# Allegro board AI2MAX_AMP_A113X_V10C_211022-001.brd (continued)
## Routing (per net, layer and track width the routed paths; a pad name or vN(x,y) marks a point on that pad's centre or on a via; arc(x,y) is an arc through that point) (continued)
VCC5V: length 170.9
  TOP w0.2: R6.2 34.96,6.79 R18.1
  TOP w0.25: R6.2 34.71,7.64 34.5,7.85 v1(34.5,8.65) ; v1(21,16.5) 21,18.1 20.25,18.85 R10.2 C10.2
  TOP w0.3: v1(73.7,38.3) 73.6,38.4 73.6,40.25 72.85,41 UNK5R5.1 ; v1(89.25,19.1) 89.25,19.25 88.85,19.65 87.75,19.65 86.95,18.85 82.1,18.85 81.85,19.1 81.6,19.1 81,19.7 78.6,19.7 v1(77.03,21.27)
  TOP w0.4: v1(55.65,9.95) v1(56.25,9.35) ; v1(45.55,9.95) v1(46.15,9.35)
  TOP w0.5: v1(44.95,9.95) 44.53,10.37 44.17,10.37 ; v1(44.95,9.95) 44.05,9.95 43.9,10.1 ; v1(44.95,9.95) v1(44.95,9.35) ; v1(44.95,9.95) 44.95,10.45 C57.1 ; v1(44.95,9.95) v1(45.55,9.95) ; 45.55,9.65 44.17,9.65 R52.2 ; 45.55,9.65 v1(45.55,9.35) ; 45.55,9.65 v1(45.55,9.95) ; v1(46.15,9.95) 45.3,10.8 44.7,10.8 ; v1(46.15,9.95) v1(46.15,9.35) v1(45.55,9.35) ; v1(46.15,9.95) v1(45.55,9.95) ; 43.9,10.1 44.17,10.37 ; 43.9,10.1 R52.2 ; 43.9,10.1 43.9,10.75 43.85,10.8 ; 43.9,10.1 43.2,10.8 ; C68.1 55.4,10.8 v1(56.25,9.95) ; C68.1 55.65,10.45 v1(55.65,9.95) ; C68.1 54.8,10.8 ; U3.5 C14.2 ; 43.2,10.8 43.85,10.8 ; 43.2,10.8 C58.2 U52.5 ; 43.85,10.8 C57.1 ; v1(55.65,9.95) v1(55.65,9.35) v1(56.25,9.35) v1(56.25,9.95) ; v1(55.65,9.95) v1(56.25,9.95) ; v1(55.65,9.95) 54.8,10.8 ; v1(45.55,9.95) 44.7,10.8 ; 44.7,10.8 C57.1 ; 44.17,10.37 C57.1 ; R52.2 43.93,9.35 v1(44.95,9.35) ; v1(78.1,26.35) v1(78.1,32.3) v1(78.1,39.1) ; v1(45.55,9.35) v1(44.95,9.35) ; 54.8,10.8 C69.2 U53.5
  MID2(L3) w0.5: 57.55,9.95 62.25,9.95 72.83,20.52 76.28,20.52 v1(77.03,21.27) 77.45,21.7 77.45,23.6 78.1,24.25 v1(78.1,26.35) ; 57.55,9.95 57.2,9.95 ; 57.55,9.95 56.35,8.75 ; v1(73.7,38.3) 74.5,39.1 v1(78.1,39.1) ; v1(56.25,9.35) 56.6,9.35 57.2,9.95 ; v1(56.25,9.35) 56.85,9.95 ; v1(56.25,9.35) v1(55.65,9.35) ; 57.2,9.95 56.85,9.95 ; 56.85,9.95 v1(56.25,9.95)
  BOTTOM w0.1: R330.1 77.85,31.35 R329.1 77.9,32.1 v1(78.1,32.3)
  BOTTOM w0.2: v1(46.15,9.35) R337.2
  BOTTOM w0.25: R17.1 v1(40,8.65)
  BOTTOM w0.4: v1(89.25,19.1) 89.25,11.95 91.1,10.1 93.7,10.1 96.25,7.55 UNK5C13.2 J814.1
  BOTTOM w0.5: 23.3,5.65 23.3,9.7 21,12 v1(21,16.5) ; 23.3,5.65 v1(23.9,5.05) ; 23.3,5.65 v1(23.3,5.05) ; v1(23.9,5.05) v1(23.3,5.05) ; v1(23.9,5.05) v1(24.5,4.45) ; v1(23.9,5.05) v1(24.5,5.05) v1(24.5,4.45) ; v1(23.3,5.05) v1(23.3,4.45) ; v1(23.3,5.05) v1(23.9,4.45) v1(24.5,3.85) ; v1(23.9,3.85) v1(23.3,3.85) v1(23.3,4.45) ; v1(23.9,3.85) v1(23.3,4.45) ; v1(23.9,3.85) v1(24.5,3.85) ; v1(34.5,8.65) v1(35.1,9.25) ; v1(34.5,8.65) v1(35.1,8.65) v1(35.1,9.25) ; v1(34.5,8.65) v1(33.9,8.65) ; v1(35.1,9.25) v1(34.5,9.25) ; U51.5 C52.2 C51.1 46.15,10.45 v1(46.15,9.95) ; v1(56.25,9.35) v1(56.25,9.95) v1(55.65,9.95) ; v1(56.25,9.35) v1(55.65,9.35) v1(55.65,9.95) ; v1(56.25,9.35) v1(55.65,9.95) ; v1(24.5,4.45) v1(24.5,3.85) ; v1(33.9,8.65) v1(33.9,9.25) v1(34.5,9.25) ; v1(33.9,8.65) v1(34.5,9.25) ; v1(78.1,39.1) 79.1,38.1 R334.1
VCC_3.3V: length 71.6
  TOP w0.25: UNK4C4.2 49.64,29.71 UNK4U5.24 ; v1(43.58,52.33) 43.64,52.27 UNK4U5.37 ; UNK4U5.12 43.64,30.43 v1(43.55,30.34) ; UNK4U5.1 38.14,29.31 UNK4C5.1
  TOP w0.254: v2(60.45,51.23) 60.39,51.17 U1.A5 ; U1.K15 66.89,44.92 v2(67.18,45.21)
  TOP w0.3: v1(49.65,28.8) UNK4C4.2 ; UNK4U9.M6 43.01,42.11 v1(43,42.1) UNK4U9.N5 ; UNK4U9.U9 44.51,40.59 v1(44.5,40.6) UNK4U9.T10
  TOP w0.406: v2(59.64,56.26) 59.64,53.6 60.45,52.78 v2(60.45,51.23)
  TOP w0.5: UNK4C4.2 50.85,29.7 51.15,30 v1(51.15,33) ; 38.15,29.05 v1(38.75,28.45) v1(38.15,28.45) 38.15,29.05 ; 38.15,29.05 UNK4C5.1 ; v1(39,62.35) v1(39,59.1) ; v1(78.7,51.7) v1(78.7,54.15)
  MID2(L3) w0.5: v1(78.7,51.7) 78.25,51.7 75.3,48.75 74.25,48.75 71.75,46.25 68.22,46.25 v2(67.18,45.21)
  BOTTOM w0.2: UNK2R19.1 v1(48.2,55.5) ; UNK2R18.1 v1(48.2,58.8)
  BOTTOM w0.3: v1(43.58,52.33) 43.56,52.3 UNK4C8.2
  BOTTOM w0.381: UNK2C22.2 60.35,51.13 v2(60.45,51.23) ; UNK5C10.2 67.42,44.98 v2(67.18,45.21)
  BOTTOM w0.4: UNK4C18.2 44.75,40.35 v1(44.5,40.6) ; UNK4C17.2 v1(43,42.1)
  BOTTOM w0.5: 38.45,28.45 v1(38.15,28.45) 38.15,29.55 ; 38.45,28.45 v1(38.75,28.45) 38.75,28.95 38.45,29.25 ; 38.45,28.45 38.45,29.25 ; 38.15,29.55 C22.1 Q1.3 ; 38.15,29.55 38.45,29.25 ; v1(49.65,28.8) 43.85,28.8 43.55,29.1 UNK4C49.2 v1(43.55,30.34) ; U55.3 51.1,32.95 v1(51.15,33) 51.5,33.35 51.5,34.5 C79.1 U55.1 49.75,34.85 48.55,36.05 v1(47.75,36.05) UNK4R6.2 ; UNK2T15.1 38,63.35 v1(39,62.35)
VDD_EE: length 100.4
  TOP w0.2: v1(38.7,5.05) 38.9,5.05 UNK1R2.2 C64.2 R53.2
  TOP w0.254: 61.02,45.55 60.77,45.3 60.73,45.3 v2(60.72,45.29) 60.7,45.26 U1.J5 ; 61.02,45.55 60.78,45.8 60.62,45.8 U1.J5 ; 61.02,45.55 U1.J6 ; U1.J5 v2(60.06,45.86) U1.J4 v2(59.41,45.85) U1.J3
  TOP w0.3: U1.F12 v2(64.62,47.2) ; U1.K11 v2(63.97,45.24)
  TOP w0.5: v1(51.15,45.75) v1(51.15,45.15)
  MID2(L3) w0.2: 45.15,15.5 44.85,15.2 ; 45.15,15.5 44.85,15.8 ; 45.15,15.5 45.15,15.2 ; 44.85,15.2 44.85,15.8 ; 44.85,15.2 45.15,15.2 ; 44.85,15.2 v1(44.4,15.65) ; 44.85,15.2 45.15,14.9 ; 45.15,14.9 47.85,12.2 61.7,12.2 75.85,26.35 v1(76.6,26.35) ; 45.15,14.9 45.15,15.2 ; 44.85,15.8 v1(44.4,16.25)
  MID2(L3) w0.3: v2(63.97,45.24) 63.35,45.86 v2(60.06,45.86)
  BOTTOM w0.1: UNK2C11.2 56.4,45.85 56.4,45.85 ; 54.94,45.65 55.08,45.51 UNK2C13.1
  BOTTOM w0.2: 44.4,15.5 v1(44.4,15.65) ; 44.4,15.5 44.4,15.05 ; 44.4,15.5 44.17,15.28 ; 44.4,15.05 44.4,12.15 43.6,11.35 43.6,5.95 42.7,5.05 v1(38.7,5.05) ; 44.4,15.05 44.17,15.28 ; R333.2 79.9,26.9 77.15,26.9 v1(76.6,26.35) ; UNK2R27.2 64.85,46.96 v2(64.62,47.2) ; 44.17,15.28 v1(43.8,15.65)
  BOTTOM w0.25: R15.2 42.8,17.25 v1(43.8,16.25)
  BOTTOM w0.3: UNK2C16.2 64.16,46.74 v2(64.62,47.2) 64.87,47.45 UNK2C1.2
  BOTTOM w0.381: UNK2C20.2 60.59,45.85 60.72,45.72 v2(60.72,45.29)
  BOTTOM w0.4: v2(63.97,45.24) 63.97,45.63 UNK2C16.2
  BOTTOM w0.5: v1(43.8,16.25) v1(43.8,15.65) v1(44.4,15.65) ; v1(43.8,16.25) v1(44.4,15.65) ; v1(43.8,16.25) v1(44.4,16.25) v1(44.4,15.65) ; 52.65,45.65 52.65,45.9 51.3,45.9 v1(51.15,45.75) v1(51.15,45.15) 51.65,45.65
  BOTTOM w0.508: UNK2C20.2 v2(59.41,45.85) 55.08,45.85 55.08,45.52
  BOTTOM w1.016: 51.65,45.65 54.94,45.65
VDDAO_3.3V: length 203.8
  TOP w0.1: v1(32,22.95) 32,23.65 32.4,24.05 R350.1 R351.1 ; v1(73.45,59.8) UNK2R24.1 UNK2R28.1
  TOP w0.2: R62.1 56.8,8.4 57.25,8.85 v1(57.25,11.2)
  TOP w0.25: v1(31.1,5.95) 30.46,6.59 C19.2 R8.2 ; v1(86.2,58.25) 87.05,59.1 R349.1 R348.1
  TOP w0.254: v2(66.57,44.59) U1.K14 ; U1.D13 65.59,48.82 v2(65.27,49.15)
  TOP w0.3: v1(86.2,58.25) 86.35,58.1 86.35,49.8 v1(86.45,49.7) ; v1(55.1,61.45) UNK2D7.1
  TOP w0.4: v1(54.75,52.25) 54.05,52.95 54.05,56.8 53.65,57.2 v1(53.65,58)
  TOP w0.5: v1(77.45,27.35) v1(77.45,32.3) v1(77.45,37.9) ; v3(67.55,56.05) 67.55,57.2 UNK2U2.3 68.23,59.37 v1(68.05,59.55) UNK2C15.2 ; v1(44.7,71.4) v1(44.1,71.4) ; v1(36.85,34.55) v1(36.85,35.15)
  MID2(L3) w0.2: 37.2,14.9 36.9,15.2 ; 37.2,14.9 37.2,15.2 ; 37.2,14.9 37.2,12.55 38.55,11.2 v1(57.25,11.2) ; 36.9,15.2 36.45,15.65 ; 36.9,15.2 37.2,15.2 ; v1(86.45,49.7) 86.05,49.3 86.05,42.8 81.15,37.9 v1(77.45,37.9) ; 37.2,15.2 37.2,15.5 37.05,15.65 36.9,15.5
  MID2(L3) w0.5: 44.7,70.8 v1(44.7,71.4) v1(44.1,71.4) 44.7,70.8 ; 44.7,70.8 45.7,69.8 45.7,61 ; v1(89.6,26.12) 88.02,27.7 v1(86.85,27.7) 77.8,27.7 v1(77.45,27.35) ; 59.85,61.7 59.85,71.42 UNK2CON1.3
  BOTTOM w0.1: v1(77.45,32.3) 75,32.3 R336.1
  BOTTOM w0.2: R314.2 27.43,59.01 v1(27.45,59.03) ; v1(89.6,26.12) 89.62,26.14 R214.2 ; R307.1 27.43,25.12 v1(27.45,25.1) ; R323.1 27.43,47.07 v1(27.45,47.05)
  BOTTOM w0.25: v1(33.26,14.89) 33.26,10.06 31.1,7.9 v1(31.1,5.95)
  BOTTOM w0.254: v2(65.27,49.15) 65.36,49.18 66.01,49.84 UNK2C5.2
  BOTTOM w0.3: U302.40 28.87,57.01 C330.1 v1(30.3,57.4) ; 66.98,51.28 66.98,51.28 UNK2C5.2 ; U201.40 88.18,50.08 C201.1 86.46,49.69 v1(86.45,49.7) ; U202.40 88.18,28.13 C230.1 86.89,27.74 v1(86.85,27.7) ; v1(30.05,35.45) C301.1 28.87,35.06 U301.40
  BOTTOM w0.305: v2(66.57,44.59) 66.71,44.45 69.09,44.45 C101.2
  BOTTOM w0.4: v1(54.75,52.25) 56.61,50.39 UNK2R2.1 ; T319.1 T129.1 71.16,61 v1(72.05,61)
  BOTTOM w0.5: v1(77.45,37.9) 77.45,37.3 R335.1 77.15,37.15 76.2,36.2 73.3,36.2 72.8,36.7 72.8,39.4 70.77,41.43 70.77,42.77 C101.2 ; 35.3,34.5 35.3,33.85 ; 35.3,34.5 C21.1 ; 35.3,34.5 R12.2 36.6,34.9 ; 35.3,34.5 36.2,34.5 ; 35.3,33.85 C23.2 C21.1 ; 35.3,33.85 35.55,33.85 36.2,34.5 ; 36.6,34.9 36.2,34.5 ; 36.6,34.9 v1(36.85,35.15) v1(36.85,34.55) 36.15,33.85 C21.1 ; v1(33.26,14.89) v1(33.26,15.49) v1(33.86,15.49) ; v1(33.26,14.89) v1(33.86,15.49) ; v1(33.26,14.89) v1(33.86,14.89) v1(33.86,15.49) ; C21.1 36.15,32.3 Q1.2 ; T316.1 45.35,67.9 C250.2 45.35,71.35 C249.1 v1(44.7,71.4) v1(44.1,71.4) ; v1(56.2,57.85) 56.2,56.86 R105.1
  BOTTOM w0.508: 66.98,51.28 67.82,52.12 67.82,55.78 v3(67.55,56.05)
VDDCPU: length 53.9
  TOP w0.2: U1.G6 61.36,47.19 61.36,47.2 61.04,47.52 U1.F6 60.71,47.2 ; U1.G6 U1.H5 60.06,46.55 ; U1.G6 61.36,46.55 61.37,46.55 v2(61.33,46.59) ; U1.G6 60.71,47.2 ; 60.71,47.2 U1.F5 60.06,47.2 ; 60.71,47.2 v2(60.68,47.2) ; 60.71,47.2 U1.G5 ; 60.06,47.2 U1.G5 ; 60.06,47.2 U1.G4 ; 60.06,46.55 59.9,46.71 ; 60.06,46.55 U1.H4 v2(59.42,46.6) ; 60.06,46.55 v2(60.08,46.59) ; 60.06,46.55 U1.G5 ; 59.9,46.71 U1.G4 ; 59.9,46.71 U1.G4 ; U1.G5 60.71,46.59 v2(60.69,46.59) ; v2(59.42,46.6) U1.H3 ; v2(59.42,46.6) U1.G3 59.09,46.87 v2(59.41,47.2) U1.G4 ; v2(59.42,46.6) U1.G4 ; v1(47.3,15.05) 47.3,14.55 47.9,13.95 47.9,6.65 48.25,6.3 v1(52.45,6.3)
  TOP w0.5: v1(46.7,16.25) v1(47.3,15.65) ; v1(46.7,16.25) v1(47.3,16.25) v1(47.3,15.65) ; v1(46.7,16.25) v1(46.7,15.65) ; v1(47.3,15.65) v1(46.7,15.65) ; v1(47.3,15.65) v1(47.3,15.05) ; v1(46.7,15.65) v1(47.3,15.05) ; v1(46.7,15.65) v1(46.7,15.05) v1(47.3,15.05) ; v1(51.55,50.1) v1(51.55,50.7) ; v1(51.55,50.1) v1(52.15,50.1) ; v1(51.55,50.1) v1(50.95,50.7) ; v1(51.55,50.1) v1(50.95,50.1) v1(50.95,50.7) ; v1(51.55,50.7) v1(52.15,50.7) v1(52.15,50.1) ; v1(51.55,50.7) v1(50.95,50.7) ; v1(51.55,50.7) v1(52.15,50.1)
  BOTTOM w0.1: v2(59.42,46.6) 59.41,46.61 v2(59.41,47.2) ; UNK2C8.2 57.81,46.9 57.8,46.89 ; 58.9,46.89 58.88,46.91 UNK2C14.2 ; UNK2C7.2 56.72,46.91 56.7,46.89 ; v2(60.68,47.2) UNK2C19.2 ; UNK2C6.1 UNK2C4.1 ; 60.2,46.54 60.15,46.59 v2(60.08,46.59)
  BOTTOM w0.102: 61.33,46.57 61.01,46.89 ; 61.33,46.57 61.34,46.56 ; 61.33,46.57 v2(61.33,46.59) ; 61.34,46.56 v2(61.33,46.59) ; 61.34,46.56 61.34,46.56 ; 61.34,46.56 61.35,46.55 61.34,46.56 ; 61.34,46.56 61.44,46.66 v2(61.33,46.59) ; v2(61.33,46.59) 61.34,46.56 ; v2(61.33,46.59) 61.32,46.55 ; 61.34,46.56 61.32,46.55 ; 61.29,46.51 61.32,46.55
  BOTTOM w0.2: v1(52.45,6.3) 51.55,6.3 UNK1R1.2 R51.2 C63.2 ; UNK2C2.2 60.07,47.01 60.2,46.89 ; UNK2C19.2 61.21,46.7 v2(61.33,46.59)
  BOTTOM w0.254: 59.43,46.54 59.43,46.65 v2(59.42,46.6) 59.43,46.54 ; 59.43,46.54 59.84,46.54 60.2,46.89
  BOTTOM w0.406: 61.34,46.57 v2(61.33,46.59) 61.36,46.59 61.36,46.61
  BOTTOM w0.508: 59.84,46.54 61.26,46.54 61.29,46.51 v2(61.33,46.59) ; v2(61.33,46.59) v2(60.69,46.59) ; v2(61.33,46.59) 61.32,46.58
  BOTTOM w1.27: UNK2C4.1 55.63,46.89 61.01,46.89
VDDCPU_EN: length 97.4
  TOP w0.1: v1(47.05,59) 47.7,58.35 48.8,58.35 49.65,57.5 49.65,56.35 50.35,55.65 50.35,52.95 51.25,52.05 53.55,52.05 v1(53.75,51.85) ; v1(45.5,7.45) 46.55,7.45 47.1,8 47.1,13.2 45.8,14.5 45.8,16.8 47.45,18.45 v1(47.45,23.9) ; v1(36.5,23.7) 36.5,26.4 35.65,27.25 35.65,55.6 v1(35,56.25)
  TOP w0.102: U1.C4 v2(59.41,49.8)
  BOTTOM w0.1: v1(53.75,51.85) 54.47,51.85 56.44,49.89 57.26,49.89 UNK2R2.2 57.76,50.4 58.81,50.4 v2(59.41,49.8) ; v1(35,56.25) 35,56.75 35.5,57.25 46.3,57.25 47.05,58 v1(47.05,59) ; v1(47.45,23.9) 42.5,23.9 42,23.4 36.8,23.4 v1(36.5,23.7)
  BOTTOM w0.2: R54.1 v1(45.5,7.45)
VDDCPU_PWM: length 94.2
  TOP w0.1: v1(34.25,53.95) 34.45,53.75 34.45,23.65 36.8,21.3 36.8,4.8 v1(37.05,4.55)
  TOP w0.102: v2(58.76,49.15) U1.D3
  BOTTOM w0.1: v1(34.25,53.95) 35.85,53.95 37.35,55.45 46.3,55.45 47.55,54.2 49.75,54.2 53.8,50.15 55.52,50.15 56.35,49.32 58.59,49.32 v2(58.76,49.15)
  BOTTOM w0.2: v1(37.05,4.55) 37.4,4.2 49.75,4.2 50.4,4.85 R56.2 UNK1R1.1
VDDEE_PWM: length 84
  TOP w0.1: R58.2 UNK1R2.1 39.55,5.05 39.05,4.55 38.1,4.55 37.3,5.35 37.3,21.6 35.25,23.65 35.25,24.05 35.05,24.25 35.05,54.35 34.45,54.95 v1(34.25,54.95)
  TOP w0.102: v2(59.41,49.15) U1.D4
  BOTTOM w0.1: v2(59.41,49.15) 59,49.56 56.45,49.56 55.11,50.9 53.75,50.9 49.95,54.7 47.76,54.7 46.51,55.95 37.05,55.95 36.05,54.95 v1(34.25,54.95)
VDDIO_AO18: length 88.9
  TOP w0.254: U1.H12 v2(65.27,45.9) ; v2(65.27,45.9) U1.J12 ; v2(65.27,45.9) U1.H13 65.83,45.97 v2(65.83,45.9) 65.83,45.81 U1.J13 65.46,45.7 v2(65.27,45.9)
  TOP w0.5: v1(77.45,40.25) 78.05,40.85 78.05,45.9 79.45,47.3 v1(79.45,51.7) v1(79.45,54.1)
  MID2(L3) w0.5: v1(55.07,57.85) 55.82,57.1 62.5,57.1 63.3,57.9 68.08,57.9 v3(68.78,57.2) 69.93,56.05 77.8,56.05 79.45,54.4 v1(79.45,54.1)
  BOTTOM w0.1: v2(65.83,45.9) 65.27,45.9 v2(65.27,45.9) ; 68.1,46.26 UNK3C1.2 ; UNK2C17.1 70.54,46.27 70.55,46.28
  BOTTOM w0.254: 66.37,45.9 66.18,45.7 65.59,45.7 UNK5C9.2
  BOTTOM w0.3: UNK2R29.2 72.95,49.05 75.05,51.15 78.9,51.15 v1(79.45,51.7)
  BOTTOM w0.4: UNK5C9.2 65.27,45.5 v2(65.27,45.9) 66.37,45.9 66.38,45.9
  BOTTOM w0.406: 66.38,45.9 UNK2C10.2
  BOTTOM w0.5: v1(77.45,40.25) UNK5R20.1 ; UNK5R20.1 75.75,41.26 73.1,43.91 73.1,44.91 ; UNK5R20.1 C76.1 U54.5 ; v1(55.07,57.85) R106.1
  BOTTOM w0.508: 70.28,46.16 UNK2C17.1 ; 70.28,46.16 70.18,46.26 68.84,46.26 ; 70.28,46.16 68.74,46.16 ; 68.84,46.26 UNK2C12.2 ; 68.84,46.26 68.1,46.26 67.82,45.98 ; 68.84,46.26 68.74,46.16 ; UNK2C10.2 66.45,45.98 67.82,45.98 ; 67.82,45.98 68.55,45.98 68.74,46.16 ; UNK2R3.2 69.11,53.93 69.11,56.87 v3(68.78,57.2)
  BOTTOM w0.61: 71.83,46.18 71.73,46.28 71.11,46.28 ; 71.83,46.18 73.1,44.91 73.1,45.42 71.95,46.56 UNK2C12.2 ; 71.83,46.18 71.22,46.18 71.11,46.28 ; 70.55,46.28 71.11,46.28
VDDIO_BOOT: length 92.4
  TOP w0.2: UNK4U9.Y4 UNK4U9.W4 ; UNK4U9.Y4 UNK4U9.AA3 v1(41.51,36.95) ; UNK4U9.Y4 UNK4U9.AA5 v1(42.51,36.95) ; v1(45.11,54.36) 44.99,54.48 UNK4R8.1 UNK4R3.1
  TOP w0.25: v1(48.3,53.46) UNK4C11.2 48.14,52.59 UNK4U5.28 ; UNK4U5.45 39.64,51.96 v1(39.15,52.45)
  TOP w0.254: UNK4U5.34 45.14,53.57 UNK4C10.2 45.11,53.64 v1(45.11,54.36)
  TOP w0.3: v2(58.82,44.53) 59.08,44.27 U1.L3 ; v1(43.2,43.1) 43.01,43.29 UNK4U9.K6
  TOP w0.5: v1(51.75,37.45) 51.75,41.15 v1(52.25,41.65) ; v1(37.45,51.3) v1(37.45,44.25) v1(37.45,38.95)
  MID2(L3) w0.5: v1(43.2,43.1) 43.2,43.9 42.85,44.25 37.45,44.25 v1(37.45,44.25) ; 39.51,38.95 v1(37.45,38.95) ; 39.51,38.95 39.7,38.76 ; 39.51,38.95 v1(39.7,38.95) ; v1(44.45,35.2) 44.45,36.15 43.65,36.95 v1(42.51,36.95) 41.7,36.95 ; 41.7,36.95 v1(39.7,38.95) ; 41.7,36.95 v1(41.51,36.95) 39.7,38.76 ; 39.7,38.76 v1(39.7,38.95)
  BOTTOM w0.1: UNK4R12.2 v1(39.7,38.95) ; v1(44.45,35.2) 44.45,31.9 UNK4R4.1 ; UNK4C34.2 43.75,43.6 UNK4R16.1
  BOTTOM w0.2: v1(41.51,36.95) 41.05,36.49 UNK4R14.1 UNK4R1.2 42.15,36.95
  BOTTOM w0.4: v1(43.2,43.1) 43.3,43.2 UNK4C34.2 ; v1(52.25,41.65) 53.85,41.65 54.4,42.2 55.22,42.2 56.53,43.51 56.97,43.51 UNK4C2.2 57.99,44.19 58.33,44.53 v2(58.82,44.53)
  BOTTOM w0.5: v1(37.45,51.3) 37.95,51.8 UNK4C48.2 v1(39.15,52.45) 39.15,52.75 39.98,53.58 42.87,53.58 43.65,54.36 v1(45.11,54.36) 45.64,54.36 46.54,53.46 v1(48.3,53.46) ; v1(41.51,36.95) v1(42.51,36.95) UNK4C35.2 UNK4C47.1 UNK4R5.1 UNK4R6.1 51.25,36.95 v1(51.75,37.45)
VDDIO_X: length 12.4
  TOP w0.254: v2(62.66,49.8) 62.34,49.47 U1.C8
  BOTTOM w0.4: v2(62.66,49.8) 62.66,50.14 62.1,50.7 C102.2 62.1,53.5 61.6,54 60.25,54 58.7,55.55 56.9,55.55 56.51,55.94 R105.2 R106.2
VDDQ1.35V: length 76.3
  TOP w0.2: v2(56.73,31.43) 56.77,31.4 56.78,31.4 57.04,31.13 UNK3U1.F1 ; v2(58.42,34.7) UNK3U1.B2 58.05,34.34 v2(57.65,34.74) 57.26,35.13 UNK3U1.A1 ; v2(64.18,23.94) 64.18,23.94 63.66,23.94 UNK3U1.R9 ; UNK3U1.N9 64.17,25.53 v2(64.17,25.53) ; v2(61.59,30.05) 61.77,30.05 UNK3U1.G7 61.67,30.71 v2(61.62,30.71) ; UNK3U1.C1 56.65,33.53 v2(56.65,33.53) ; 63.68,32.73 UNK3U1.D9 63.65,32.69 v2(63.27,32.31) UNK3U1.E9 63.65,31.94 v2(64.06,32.35) 63.68,32.73 ; 63.68,32.73 63.7,32.73 v2(64.12,33.15) 64.03,33.15 UNK3U1.C9 ; v1(53.5,6.3) 53.5,6.8 52.95,7.35 R61.2 C74.2 ; U1.M10 v2(63.97,43.94) U1.M11 ; v2(56.69,23.83) 56.79,23.93 UNK3U1.R1 ; v2(62.41,35.54) 62.44,35.54 UNK3U1.A8 ; v2(62.44,27.52) UNK3U1.K8 ; UNK3U1.H2 v2(57.69,29.17) ; v2(58.42,28.31) 58.05,27.94 UNK3U1.K2 ; U1.M8 v2(62.01,43.29) 61.69,43.62 U1.M7 v2(61.36,43.29) U1.M6 ; v2(64.12,29.59) 63.71,29.59 63.65,29.54 UNK3U1.H9 ; 60.39,42.97 U1.N5 v2(60.06,42.64) 59.74,42.97 U1.N4 v2(60.06,43.29) 60.39,42.97
  TOP w0.3: UNK3U1.D2 58.44,32.34 v2(58.46,32.34) ; UNK3U1.N1 57.24,25.52 v2(56.68,25.52)
  BOTTOM w0.2: 54.73,13.38 54.5,13.6 ; 54.73,13.38 54.5,13.15 ; 54.73,13.38 v1(55.1,13.75) ; 54.5,13.6 v1(54.5,13.75) ; 54.5,13.6 54.5,13.15 ; 54.5,13.15 54.5,7.3 v1(53.5,6.3)
  BOTTOM w0.3: 64.36,33.39 UNK3C58.2 64.23,33.96 64.1,33.96 ; 64.36,33.39 v2(64.12,33.15) 63.82,32.85 UNK3C38.2 ; 64.36,33.39 64.36,32.65 64.1,32.39 ; 63.6,33.96 UNK3C42.2 63.3,33.95 UNK3C38.2 ; 63.6,33.96 63.8,33.96 ; 63.6,33.96 63.6,32.64 63.31,32.35 ; UNK3C21.2 57,33.18 v2(56.65,33.53) ; 64.1,32.39 v2(64.06,32.35) 63.6,32.35 ; 64.1,32.39 64.1,33.96 ; UNK3C38.2 63.27,32.82 v2(63.27,32.31) 63.31,32.35 ; 63.31,32.35 63.6,32.35 ; UNK3C4.2 64.54,43.37 v2(63.97,43.94) ; 64.1,33.96 63.8,33.96 ; 63.6,32.35 63.8,32.55 63.8,33.96
  BOTTOM w0.381: UNK3C2.2 56.42,31.74 v2(56.73,31.43)
  BOTTOM w0.4: v2(54.34,27.56) 54.87,27.56 UNK3R19.2 54.94,27.49 v2(54.94,26.9) ; 59.55,42.65 59.82,42.65 UNK3C39.2 ; 59.55,42.65 UNK3C62.2 ; 59.55,42.65 60.06,43.16 ; UNK3C62.2 59.16,42.64 v2(60.06,42.64) 60.06,42.71 ; UNK3C62.2 58.35,41.85 UNK3C31.2 56.65,40.28 UNK3C28.1 ; v2(58.42,28.31) 58.42,28.7 UNK3C26.1 ; UNK3C10.2 58.42,35.18 v2(58.42,34.7) ; 60.06,42.71 60.06,43.16 ; 60.06,42.71 60.53,43.18 UNK3C39.2 ; 60.06,43.16 v2(60.06,43.29) 60.13,43.36 UNK3C39.2 ; UNK3C18.2 56.66,25.5 v2(56.68,25.52) 56.8,25.52 UNK3C6.1 ; v2(64.17,25.53) 64.62,25.53 UNK3C30.2 ; UNK3C11.2 58.51,32.28 v2(58.46,32.34) ; v2(61.59,30.05) 61.06,30.05 UNK3C8.1 61.16,30.71 v2(61.62,30.71) ; UNK3C19.2 57.38,29.49 v2(57.69,29.17) ; v2(64.18,23.94) 63.92,24.21 UNK3C12.2 ; v2(57.65,34.74) 57.65,35.12 UNK3C9.2 ; v2(64.12,29.59) 63.62,29.59 UNK3C45.2
  BOTTOM w0.406: v2(62.01,43.29) 61.37,43.29 v2(61.36,43.29)
  BOTTOM w0.5: v2(62.41,35.54) 62.51,35.64 UNK3C20.2 ; UNK3C35.2 56.69,23.42 ; 56.69,23.42 57.17,23.42 UNK3R8.2 ; 56.69,23.42 v2(56.69,23.83) ; v2(56.69,23.83) 57.15,23.37 UNK3R8.2 ; v2(56.69,23.83) 56.81,23.83 57.22,24.24 ; UNK3R8.2 57.22,24.24 ; 57.22,24.24 UNK3C6.1 ; UNK3C19.2 58.2,29.7 58.7,29.2 UNK3C26.1 ; v1(55.1,13.75) v1(54.5,13.75) v1(54.5,14.35) ; v1(55.1,13.75) v1(55.1,14.35) v1(54.5,14.35) ; v1(55.1,13.75) v1(54.5,14.35) ; v2(62.01,43.29) 61.98,43.33 UNK3C5.2
  vias: v4(54.33,38.06) v4(54.35,39.07)
ACTIVE_STBY: length 123.9
  TOP w0.1: v1(60.7,16.5) 60.3,16.9 59.75,16.9 59.5,17.15 59.5,17.6 53.85,23.25 53.85,23.65 53.3,24.2 v1(53,24.2) ; U1.B11 64.62,50.45 64.62,50.93 64.18,51.36 64.18,54.98 64.95,55.75 64.95,58.85 v1(64.75,59.05) ; v1(38.3,25.4) 37.8,25.9 37.3,25.9 35.85,27.35 35.85,56.05 v1(35.65,56.25) ; v1(71.64,15.5) 71.8,15.5 72.6,16.3 79.45,16.3 81,14.75 R219.1
  BOTTOM w0.1: v1(35.65,56.25) 36.25,56.85 46.5,56.85 47.8,58.15 47.8,59.05 48.1,59.35 50.45,59.35 50.75,59.05 v1(64.75,59.05) ; v1(60.7,16.5) 60.9,16.3 70.14,16.3 70.54,15.9 71.24,15.9 v1(71.64,15.5) ; v1(53,24.2) 52.6,24.6 52,24.6 51,25.6 42,25.6 40.7,24.3 38.8,24.3 38.3,24.8 v1(38.3,25.4) 37.75,25.95 R320.1
AMP_RESET: length 105.2
  TOP w0.1: R215.1 v1(82,13.4) 82,14.35 79.65,16.7 72.3,16.7 71.9,16.3 v1(71.64,16.3) ; v1(53,25) 53.1,25 54.25,23.85 54.25,23.42 59.97,17.7 60.3,17.7 v1(60.7,17.3) ; v1(35.85,60.2) 35.7,60.05 35.7,57.45 36.25,56.9 36.25,27.55 37.45,26.35 40.3,26.35 v1(40.65,26)
  BOTTOM w0.1: v1(60.7,17.3) 60.75,17.3 61.35,16.7 71.24,16.7 v1(71.64,16.3) ; UNK5R74.2 v1(82,13.4) ; R315.1 v1(40.65,26) 52,26 v1(53,25) ; v1(35.85,60.2) 35.6,59.95 33.85,59.95 33.55,60.25 33.55,63.9 36.3,66.65 41.6,66.65 42.08,67.12
  BOTTOM w0.3: T317.1 42.08,67.12
AMP_SCL: length 67.4
  TOP w0.1: UNK2R24.2 v1(75,59.05) ; v1(80.75,59) 80.75,57.8 81.3,57.25 81.3,54.25 81.85,53.7 81.85,48.25 82.1,48 82.1,33.55 82.9,32.75 82.9,20.1 v1(83.1,19.9)
  TOP w0.102: v1(75,59.05) 75.4,58.65 75.4,57.8 74.74,57.14 71.86,57.14 69.3,54.57 69.3,53.46 67.54,51.69 U1.A16
  BOTTOM w0.1: v1(83.1,19.9) 82.9,19.7 81.65,19.7 80.2,18.25 80.2,16.3 80.9,15.6 UNK5R66.2 ; v1(80.75,59) 79.75,59 79.15,59.6 76.35,59.6 R209.1 v1(75,59.05)
AMP_SCL_DEV: length 66.1
  TOP w0.1: v1(77.3,61.3) 77.45,61.15 77.45,59.25 v1(77.25,59.05) ; v1(36.15,59.05) 36.55,59.45 36.55,60.65 v1(36.8,60.9) ; R309.1 46.35,57.7 45.8,58.25 v1(45.8,58.45)
  BOTTOM w0.1: v1(36.15,59.05) 36.55,58.65 37,58.65 37.15,58.5 37.7,58.5 38.15,58.05 45.4,58.05 v1(45.8,58.45) ; v1(36.8,60.9) 37.2,61.3 37.2,63.85 37.6,64.25 46.1,64.25 46.65,64.8 61.65,64.8 62.65,65.8 63.2,65.8 64.1,66.7 68.05,66.7 69.2,67.85 69.6,67.85 ; R238.1 v1(77.25,59.05) R209.2 ; 71.2,67.85 71.55,67.85 72.6,66.8 72.6,64.1 75.2,61.5 77.1,61.5 v1(77.3,61.3)
  BOTTOM w0.3: 69.6,67.85 T306.1 71.2,67.85
AMP_SDA: length 69.5
  TOP w0.1: v1(75,57.95) UNK2R28.2 73.75,57.35 71.77,57.35 ; v1(83.75,19.9) 83.1,20.55 83.1,32.87 82.3,33.67 82.3,48.15 82.05,48.4 82.05,53.8 81.51,54.34 81.51,57.74 v1(81.25,58)
  TOP w0.102: U1.B15 66.89,50.27 67.21,50.59 67.21,51.67 69.09,53.55 69.09,54.66 71.77,57.35
  BOTTOM w0.1: v1(83.75,19.9) 83.35,19.5 81.75,19.5 80.4,18.15 80.4,16.4 81.45,15.35 81.45,13.85 80.9,13.3 UNK5R65.2 ; v1(75,57.95) R210.1 76.35,57.4 79.2,57.4 80,58.2 81.05,58.2 v1(81.25,58)
AMP_SDA_DEV: length 69.4
  TOP w0.1: v1(77.95,61.3) 77.65,61 77.65,58.35 v1(77.25,57.95) ; R310.1 46,57.1 46,57.45 45.2,58.25 v1(45.2,58.45) ; v1(36.75,59.05) 36.75,60.25 37.2,60.7 37.2,61.1 v1(36.8,61.5)
  BOTTOM w0.1: R239.1 v1(77.25,57.95) R210.2 ; v1(77.95,61.3) 77.55,61.7 75.3,61.7 72.8,64.2 72.8,67.2 ; 72.22,68.42 72,68.65 69.7,68.65 67.95,66.9 64,66.9 63.1,66 62.55,66 61.55,65 46.55,65 46,64.45 37.45,64.45 37,64 37,61.7 v1(36.8,61.5) ; v1(36.75,59.05) 36.9,59.05 37.25,58.7 37.85,58.7 38.3,58.25 45,58.25 v1(45.2,58.45)
  BOTTOM w0.3: 72.8,67.2 T305.1 72.22,68.42
BCLK: length 5.6
  BOTTOM w0.102: UNK5R68.1 78.5,10.75 79.65,9.6 81.3,9.6 82.18,8.72 J813.11
CPU_RESET: length 126.6
  TOP w0.1: v1(71.65,17.1) 79.85,17.1 81.7,15.25 83.9,15.25 R240.1 ; v1(53,25.7) 54.45,24.25 54.45,23.52 60.07,17.9 60.9,17.9 v1(61.5,17.3) ; v1(37.55,58.05) 37.55,57.65 36.85,56.95 36.85,36.8 37.3,36.35 37.3,34.35 36.65,33.7 36.65,27.6 37.6,26.65 40.25,26.65 v1(40.65,27.05) ; v1(65.55,59.65) 65.55,59.35 65.35,59.15 65.35,57.61 UNK2U2.2 65.74,56.64 UNK2R14.1 65.73,55.47 64.89,54.63 64.89,51.83 64.63,51.56 64.63,51.25 64.94,50.94 U1.A12
  BOTTOM w0.1: v1(53,25.7) 52.5,26.2 41.5,26.2 v1(40.65,27.05) 40.6,27.1 R338.1 ; v1(37.55,58.05) 37.75,57.85 45.95,57.85 46.25,58.15 46.25,59.4 46.7,59.85 47.35,59.85 47.65,60.15 50.9,60.15 51.2,59.85 58.9,59.85 59.3,60.25 60.45,60.25 61.05,59.65 63.6,59.65 64,60.05 65.15,60.05 v1(65.55,59.65) ; v1(61.5,17.3) 61.9,16.9 71.45,16.9 v1(71.65,17.1)
CTRL_A113X: length 2.7
  BOTTOM w0.1: UNK5R75.2 UNK5R77.1 UNK5R76.1
DATA: length 8.2
  BOTTOM w0.102: UNK5R69.1 78,13.65 78,10.65 79.35,9.3 81.1,9.3 81.68,8.72 J813.12
DDR3_A0: length 28.5
  TOP w0.102: v2(64.62,41.34) U1.R12 ; v2(60.55,24.73) 60.08,24.73 59.28,25.53 UNK3U1.N3
  BOTTOM w0.102: v2(64.62,41.34) 64.62,41.21 64.26,40.86 64.26,40.62 64.54,40.34 64.79,40.34 65.91,39.22 66.67,39.22 68.54,37.35 68.54,26.89 66.55,24.89 65.76,24.89 65.53,25.12 63.85,25.12 63.73,25 60.82,25 v2(60.55,24.73)
DDR3_A1: length 24.7
  TOP w0.1: v2(62.44,24.35) 62.06,24.73 UNK3U1.P7
  TOP w0.102: U1.U15 66.95,40.31 66.95,39.68 69.12,37.51 69.12,26.66 66.1,23.64 v2(65.9,23.64)
  BOTTOM w0.102: v2(62.44,24.35) 62.81,23.98 62.81,23.27 63.35,22.74 65.2,22.74 65.9,23.43 v2(65.9,23.64)
DDR3_A2: length 34.8
  TOP w0.102: v2(67.87,41.99) U1.P16 ; v2(59.65,23.76) 59.65,24.3 59.22,24.73 UNK3U1.P3
  BOTTOM w0.102: v2(67.87,41.99) 68.27,41.59 68.27,41.3 68.76,40.82 69.31,40.82 71.3,38.84 71.3,25.76 66.42,20.88 63.09,20.88 60.21,23.76 v2(59.65,23.76)
DDR3_A3: length 35.7
  TOP w0.102: U1.U17 70.43,38.13 70.43,26.11 65.48,21.16 59.41,21.16 58.36,22.21 57.6,22.21 56.34,23.47 56.34,24.98 56.5,25.15 57.39,25.15 57.77,25.53 UNK3U1.N2
DDR3_A4: length 24.6
  TOP w0.102: UNK3U1.P8 63.24,25.12 64.95,25.12 v2(65.35,25.53) ; v2(64.54,41.94) 64.29,41.69 U1.R11
  BOTTOM w0.102: v2(65.35,25.53) 65.54,25.53 65.9,25.17 66.42,25.17 68.25,27 68.25,37.29 66.55,38.98 65.79,38.98 64.65,40.12 64.4,40.12 63.97,40.55 63.97,40.93 64.26,41.23 64.26,41.66 v2(64.54,41.94)
DDR3_A5: length 30.3
  TOP w0.102: UNK3U1.P2 58.22,24.73 58.62,25.14 59.24,25.14 60.03,24.35 60.03,23.56 59.87,23.4 59.87,22.96 60.09,22.74 64.77,22.74 65.15,23.12 65.15,23.9 65.86,24.61 66.27,24.61 68.54,26.89 68.54,37.35 66.44,39.45 66.44,39.91 66.29,40.06 66.11,40.06 65.94,40.23 65.94,40.54 66.17,40.77 66.17,40.94 U1.T14
DDR3_A6: length 24.4
  TOP w0.102: UNK3U1.R8 63.26,24.34 65.05,24.34 v2(65.39,24.68) ; v2(65.27,41.99) U1.P12
  BOTTOM w0.102: v2(65.39,24.68) 65.45,24.61 66.67,24.61 68.83,26.77 68.83,37.42 65.27,40.98 v2(65.27,41.99)
DDR3_A7: length 29.3
  TOP w0.102: UNK3U1.R2 58.44,24.32 59.08,24.32 59.24,24.16 59.24,23.21 59.99,22.46 64.92,22.46 65.45,22.99 65.45,23.8 65.99,24.34 66.39,24.34 68.83,26.77 68.83,37.42 66.7,39.55 66.7,40.06 66.4,40.35 66.24,40.35 U1.U14
DDR3_A8: length 25.1
  TOP w0.102: U1.P13 65.85,42.06 v2(65.85,42.04) ; v2(64.77,23.93) 64.39,23.55 63.27,23.55 UNK3U1.T8
  BOTTOM w0.102: v2(65.85,42.04) 65.56,41.74 65.56,41.07 69.12,37.51 69.12,26.66 66.77,24.31 65.4,24.31 65.02,23.93 v2(64.77,23.93)
DDR3_A9: length 31.6
  TOP w0.102: UNK3U1.R3 58.47,23.55 58.47,22.91 58.62,22.76 58.62,22.35 59.54,21.44 65.38,21.44 70.13,26.19 70.13,38.03 68.15,40.01 68.07,40.01 67.87,40.21 67.87,40.69 U1.T16
DDR3_A10: length 22.8
  TOP w0.102: U1.R10 63.64,41.67 63.89,41.42 v2(63.9,41.42) ; UNK3U1.L7 62.43,26.75 66.72,26.75 v2(67,27.03)
  BOTTOM w0.102: v2(67,27.03) 67.94,27.97 67.94,37.19 66.41,38.72 65.7,38.72 64.56,39.85 64.3,39.85 63.66,40.49 63.66,41.18 v2(63.9,41.42)
DDR3_A11: length 35.3
  TOP w0.102: U1.P17 68.2,42.32 v2(68.53,41.99) ; v2(60.25,23.14) 60.35,23.04 61.42,23.04 62.05,23.67 UNK3U1.R7
  BOTTOM w0.102: v2(60.25,23.14) 60.45,23.14 62.99,20.6 66.55,20.6 71.58,25.63 71.58,38.97 69.44,41.1 68.88,41.1 68.56,41.42 68.56,41.97 68.54,41.99 v2(68.53,41.99)
DDR3_A12: length 30.8
  TOP w0.102: U1.T17 68.19,41.02 68.58,41.02 69.04,40.57 v2(69.04,40.08) ; v2(61.42,23.62) 61.41,23.63 61.67,23.89 61.67,25.15 UNK3U1.N7
  BOTTOM w0.102: v2(61.42,23.62) 61.42,23.34 63.32,21.44 66.17,21.44 70.74,26.01 70.74,38.38 v2(69.04,40.08)
DDR3_A13: length 29
  TOP w0.102: UNK3U1.T3 58.94,23.13 59.89,22.18 65.07,22.18 69.42,26.52 69.42,37.59 67.21,39.8 67.21,41.31 66.87,41.65 U1.R15
DDR3_A14: length 27.6
  TOP w0.1: v2(62.42,23.51) 62.05,23.14 UNK3U1.T7
  TOP w0.102: v2(66.51,41.42) 66.49,41.42 U1.R14
  BOTTOM w0.102: v2(66.51,41.42) 66.74,41.42 70.13,38.03 70.13,26.19 66.39,22.46 63.21,22.46 62.42,23.24 v2(62.42,23.51)
DDR3_A15: length 29.2
  TOP w0.102: UNK3U1.M7 61.29,25.57 v2(61.29,24.54) ; v2(65.92,41.34) 65.59,41.02 U1.T13
  BOTTOM w0.102: v2(61.29,24.54) 61.47,24.72 62.66,24.72 63.14,24.23 63.14,23.88 63.32,23.7 63.9,23.7 64.03,23.57 65.12,23.57 65.58,24.03 66.93,24.03 69.42,26.52 69.42,37.63 67.64,39.41 67.64,40.13 66.72,41.05 66.21,41.05 v2(65.92,41.34)
DDR3_BA0: length 41
  TOP w0.102: UNK3U1.M2 57.66,25.94 56.47,25.94 56.03,25.49 56.03,23.37 57.45,21.95 58.21,21.95 59.28,20.88 65.61,20.88 70.74,26.01 70.74,38.39 69.47,39.66 69.47,41.62 68.31,42.78 67.75,42.78 67.56,42.97 U1.N16
DDR3_BA1: length 20.5
  TOP w0.102: U1.U12 64.94,40.01 65.12,39.83 65.12,39.65 65.78,38.99 66.14,38.99 67.94,37.19 67.94,27.1 66.77,25.94 63.26,25.94 UNK3U1.N8
DDR3_BA2: length 45
  TOP w0.102: UNK3U1.M3 58.44,26.74 56.55,26.74 55.73,25.91 55.73,23.37 58.77,20.32 65.86,20.32 71.3,25.76 71.3,38.84 70,40.13 70,41.76 68.48,43.28 68.01,43.28 67.67,43.62 U1.M16
DDR3_CAS: length 35.4
  TOP w0.102: UNK3U1.K3 59.82,27.93 60.91,26.85 v2(60.91,23.98) ; U1.P15 66.89,42.32 v2(66.57,41.99)
  BOTTOM w0.102: v2(60.91,23.98) 61.56,23.98 61.92,23.62 61.92,23.31 63.06,22.18 66.5,22.18 70.43,26.11 70.43,38.13 v2(66.57,41.99)
DDR3_CKE0: length 19
  TOP w0.102: v2(66.55,28.17) 65.94,28.17 65.7,27.94 63.66,27.94 UNK3U1.K9 ; U1.P10 63.64,42.32 v2(63.32,41.99)
  BOTTOM w0.102: v2(63.32,41.99) 63.3,41.99 62.9,41.59 62.9,39.93 66.5,36.34 66.5,28.22 v2(66.55,28.17)
DDR3_CLKN: length 20.6
  TOP w0.102: v2(65.33,28.58) 66.42,29.67 66.42,36.25 64.57,38.1 UNK3C7.1 64.14,38.43 63.66,38.9 63.66,39.37 63.65,39.39 63.65,39.4 63.32,39.73 63.32,40.6 63.63,40.91 63.63,41.01 U1.T10 ; v2(61.3,28.04) 61.33,28.07 61.45,28.2 61.96,28.2 62.05,28.1 UNK3U1.K7
  BOTTOM w0.102: v2(65.33,28.58) 65.33,28.56 65.19,28.43 61.8,28.43 61.45,28.08 61.42,28.08 v2(61.3,28.04) 61.29,28.05 61.29,28.06 61.15,28.21 60.94,28.21 UNK3R2.2
DDR3_CLKP: length 19.4
  TOP w0.102: U1.U9 63.04,40.32 63.04,39.6 63.38,39.26 63.38,38.79 63.85,38.32 UNK3C7.2 64.56,37.71 66.14,36.13 66.14,29.8 65.62,29.28 65.42,29.28 v2(65.4,29.26) ; v2(61.26,28.68) 61.31,28.64 61.48,28.48 61.97,28.48 62.05,28.55 UNK3U1.J7
  BOTTOM w0.1: UNK3R2.1 61.09,28.68 v2(61.26,28.68)
  BOTTOM w0.102: v2(61.26,28.68) 61.32,28.64 61.38,28.7 64.84,28.7 v2(65.4,29.26)
DDR3_DQ0: length 7.1
  TOP w0.1: 57.12,36.06 57.12,36.06 UNK3U1.A2
  TOP w0.102: U1.T2 58.44,41.02 58.28,41.02 57.95,40.69 57.66,40.69 57.12,40.16 57.12,36.06
DDR3_DQ1: length 9.9
  TOP w0.102: U1.T3 59.08,41.01 59.08,40.87 58.77,40.57 58.77,39.79 58.44,39.46 58.44,36.79 59.51,35.73 59.51,33.66 58.98,33.13 58.67,33.13 58.27,33.53 UNK3U1.C2
DDR3_DQ2: length 8.3
  TOP w0.102: v2(60.71,41.99) U1.P6 ; UNK3U1.A7 61.82,35.36 61.82,35.88 v2(61.92,35.98)
  BOTTOM w0.102: v2(60.71,41.99) 60.71,41.99 61.14,41.57 61.14,41.02 60.81,40.69 60.81,37 61.8,36 61.9,36 v2(61.92,35.98)
DDR3_DQ3: length 10.3
  TOP w0.102: U1.U7 61.85,40.24 61.85,37.09 63.04,35.89 63.69,35.89 64.01,35.58 64.01,34.15 63.79,33.94 63.45,33.94 63.26,33.74 63.26,33.37 63.03,33.14 62.55,33.14 62.14,32.73 UNK3U1.D7
DDR3_DQ4: length 6.1
  TOP w0.102: UNK3U1.A3 58.39,35.59 58.13,35.59 57.43,36.29 57.43,40.01 U1.U1
DDR3_DQ5: length 7.6
  TOP w0.102: UNK3U1.C3 58.86,33.53 59.21,33.88 59.21,35.58 58.14,36.64 58.14,39.59 58.44,39.89 U1.U2
DDR3_DQ6: length 8.5
  TOP w0.102: UNK3U1.B8 v2(62.44,34.74) ; U1.R6 61.04,41.66 v2(60.78,41.4)
  BOTTOM w0.102: v2(60.78,41.4) 60.78,41.05 60.5,40.77 60.5,36.85 62.44,34.9 v2(62.44,34.74)
DDR3_DQ7: length 8.6
  TOP w0.102: UNK3U1.C8 62.85,33.81 63.24,34.21 63.24,35.26 61.54,36.96 61.54,40.05 61.36,40.22 61.36,40.55 61.69,40.87 U1.T7
DDR3_DQ8: length 15.3
  TOP w0.102: UNK3U1.H7 62.29,29.53 62.74,29.97 64.3,29.97 65,30.67 65,35.61 64.01,36.6 63.37,36.6 62.56,37.42 62.56,38.99 62.25,39.3 62.25,40.93 U1.T8
DDR3_DQ9: length 13.7
  TOP w0.102: UNK3U1.F2 57.66,31.52 57.15,31.52 56.84,31.83 56.28,31.83 55.62,32.49 55.62,35.79 56.41,36.58 56.41,40.27 57.48,41.34 57.9,41.34 58.25,41.69 58.43,41.69 U1.R2
DDR3_DQ10: length 16.2
  TOP w0.102: U1.R9 62.66,41.34 62.66,40.86 62.48,40.68 62.48,39.38 62.86,39 62.86,37.56 63.54,36.88 64.18,36.88 65.3,35.77 65.3,30.52 64.49,29.71 64.49,29.46 64.2,29.17 63.21,29.17 UNK3U1.H8
DDR3_DQ11: length 11
  TOP w0.1: v2(59.15,32.26) 58.85,31.96 UNK3U1.E3
  TOP w0.102: v2(59.41,41.34) U1.R4
  BOTTOM w0.102: v2(59.15,32.26) 58.89,32.52 58.89,33.25 60.04,34.4 60.04,35.87 59.23,36.68 59.23,41.16 v2(59.41,41.34)
DDR3_DQ12: length 14.9
  TOP w0.102: UNK3U1.F8 63.22,31.5 v2(63.22,31.52) ; v2(61.99,41.96) U1.R7
  BOTTOM w0.102: v2(63.22,31.52) 64.54,31.52 65.3,32.29 65.3,35.76 64.15,36.91 63.57,36.91 61.85,38.64 61.85,41.1 61.75,41.2 61.75,41.59 v2(61.99,41.96)
DDR3_DQ13: length 17.4
  TOP w0.102: U1.P1 57.79,42.32 57.02,42.32 55.4,40.69 55.4,37.06 54.61,36.27 54.61,31.97 56.65,29.92 58.29,29.92 58.68,29.53 UNK3U1.H3
DDR3_DQ14: length 17
  TOP w0.102: v2(62.71,42.04) 62.97,42.3 U1.P9 ; v2(62.46,30.74) 62.06,31.13 UNK3U1.F7
  BOTTOM w0.102: v2(62.46,30.74) 62.85,30.34 63.5,30.34 63.89,30.73 64.88,30.73 66.04,31.89 66.04,36.13 62.58,39.59 62.58,41.91 v2(62.71,42.04)
DDR3_DQ15: length 14.2
  TOP w0.102: U1.R1 57.78,41.68 57.4,41.68 56.11,40.39 56.11,36.71 55.32,35.92 55.32,32.32 56.91,30.74 57.64,30.74 UNK3U1.G2
DDR3_DQM0: length 10.4
  TOP w0.102: v2(60.06,41.34) U1.R5 ; v2(59.36,32.96) 59.13,32.73 UNK3U1.D3
  BOTTOM w0.102: v2(59.36,32.96) 59.36,33.17 60.37,34.19 60.37,36.05 59.56,36.86 59.56,40.84 v2(60.06,41.34)
DDR3_DQM1: length 15.8
  TOP w0.1: v2(61.57,31.93) UNK3U1.E7
  TOP w0.102: v2(61.43,42.08) 61.67,42.32 U1.P7
  BOTTOM w0.102: v2(61.57,31.93) 64.43,31.93 64.93,32.44 64.93,35.66 64.01,36.58 63.45,36.58 61.54,38.48 61.54,41.77 61.43,41.89 v2(61.43,42.08)
DDR3_DQSN0: length 7.9
  TOP w0.102: U1.T6 60.73,40.7 60.73,37.01 61.21,36.53 61.21,34.56 61.69,34.09 61.81,34.09 UNK3U1.B7
DDR3_DQSN1: length 13.3
  TOP w0.102: UNK3U1.G3 59.09,30.33 59.22,30.46 arc(59.25,30.53) 59.22,30.59 59.11,30.71 arc(59.08,30.77) 59.11,30.84 59.19,30.92 arc(59.25,30.95) 59.31,30.92 59.43,30.8 arc(59.5,30.77) 59.56,30.8 59.65,30.89 arc(59.68,30.95) 59.65,31.02 59.54,31.13 arc(59.51,31.19) 59.54,31.26 59.61,31.33 arc(59.68,31.36) 59.74,31.33 59.85,31.22 arc(59.92,31.19) 59.98,31.22 60.04,31.28 60.04,31.55 arc(60.02,31.61) 59.95,31.64 59.89,31.64 arc(59.83,31.66) 59.8,31.73 59.8,31.84 arc(59.83,31.9) 59.89,31.93 59.95,31.93 arc(60.02,31.96) 60.04,32.02 60.04,35.98 59.26,36.77 59.26,39.32 59.48,39.55 59.48,40.13 59.41,40.21 59.41,40.69 U1.T4
DDR3_DQSP0: length 7.6
  TOP w0.102: U1.U5 60.45,40.31 60.45,36.9 60.93,36.41 60.93,34.46 61.57,33.82 61.76,33.82 62.05,33.54 UNK3U1.C7
DDR3_DQSP1: length 13.3
  TOP w0.102: UNK3U1.F3 58.77,31.13 58.47,30.83 58.47,30.14 58.67,29.94 59.1,29.94 60.32,31.16 60.32,36.1 59.54,36.88 59.54,39.19 59.76,39.42 59.76,40.37 U1.U4
DDR3_NCS0: length 23.4
  TOP w0.102: UNK3U1.L2 58.47,27.55 59.7,27.55 v2(59.9,27.35) ; v2(66.04,27.71) 66.75,27.71 67.23,28.2 67.23,36.86 64.72,39.37 64.72,39.63 64.36,39.98 64.36,40.29 64.29,40.36 U1.U11
  BOTTOM w0.102: v2(59.9,27.35) 59.98,27.27 61.63,27.27 62.25,27.89 65.86,27.89 v2(66.04,27.71)
DDR3_ODT0: length 37.6
  TOP w0.1: v2(56.65,27.33) UNK3U1.K1
  TOP w0.102: v2(67.84,41.37) 67.84,41.37 U1.R16
  BOTTOM w0.102: v2(67.84,41.37) 68.69,40.52 69.13,40.52 71.02,38.64 71.02,25.89 66.29,21.16 63.19,21.16 59,25.35 59,26.04 58.24,26.8 57.19,26.8 v2(56.65,27.33)
DDR3_RAS: length 24.7
  TOP w0.102: UNK3U1.J3 59.74,28.73 61.62,26.86 v2(61.62,26.7) ; U1.T11 64.31,41 64.24,40.92 64.24,40.82 63.98,40.57 63.98,40.16 64.08,40.06 64.08,39.88 64.34,39.63 v2(64.34,39.42)
  BOTTOM w0.102: v2(61.62,26.7) 66.09,26.7 67.23,27.84 67.23,36.86 64.67,39.42 v2(64.34,39.42)
DDR3_RST: length 37.9
  TOP w0.1: v2(58.21,22.57) 58.05,22.74 UNK3U1.T2
  TOP w0.102: v2(58.24,21.39) 59.03,20.6 65.73,20.6 71.02,25.89 71.02,38.64 69.72,39.93 69.72,41.68 68.37,43.03 67.93,43.03 67.67,43.29 67.22,43.29 U1.M15
  BOTTOM w0.1: v2(58.24,21.39) 58.19,21.44 UNK3C46.2 58.19,22.54 v2(58.21,22.57) 58.24,22.59 UNK3R8.1
DDR3_WE: length 28
  TOP w0.102: v2(60.2,25.28) 60.2,26.1 59.17,27.13 UNK3U1.L3 ; v2(66.14,25.55) 66.8,25.55 68.25,27 68.25,37.28 66.28,39.25 65.9,39.25 65.39,39.76 65.39,39.97 65.28,40.08 65.28,41.36 U1.R13
  BOTTOM w0.102: v2(66.14,25.55) 65.66,26.04 64.35,26.04 64.25,25.94 63.8,25.94 63.14,25.28 v2(60.2,25.28)
EMMC_1.8V: length 3.1
  BOTTOM w0.5: U55.5 47.15,34.6 C77.1 UNK4R5.2
GPIOX_16: length 7.5
  TOP w0.102: v2(63.32,49.15) 63.64,48.82 U1.D10
  BOTTOM w0.1: v2(63.32,49.15) 63.38,49.21 63.38,50.27 63.55,50.43 63.55,51.5 62.48,52.57 62.48,55.14 T125.1
GPIOX_17: length 5.1
  TOP w0.102: v2(62.01,49.15) U1.D8
  BOTTOM w0.1: T126.1 61.62,52.88 61.62,50.68 62.3,49.99 62.3,49.44 v2(62.01,49.15)
GPIOX_18: length 3.5
  TOP w0.102: v2(63.97,49.8) U1.C10
  BOTTOM w0.1: T127.1 63.95,52.03 64.29,51.69 64.29,50.12 v2(63.97,49.8)
GPIOZ_10: length 4.6
  TOP w0.1: UNK2T3.1 55.88,50.6 55.98,50.5 55.98,49.89 57.61,48.26 58.35,48.26 U1.E2
HW_VS: length 5
  TOP w0.102: v2(67.22,49.15) U1.D15
  BOTTOM w0.1: v2(67.22,49.15) 68.02,49.95 68.77,50.7 69.4,50.7 UNK2R15.2 69.8,52.22 UNK2R3.1
I2SIN_BCLK_C: length 170.2
  TOP w0.1: R107.2 v1(76.7,45.1) ; v1(79.9,44.2) 79.9,32.07 80.25,31.72 v1(80.25,20.7) ; v1(84.85,60.4) 84.3,59.85 84.3,56.9 84.95,56.25 v1(84.95,47) v1(84.95,44.2) 84.95,38.35 84.25,37.65 84.25,25.95 v1(85.15,25.05) ; v1(31.9,38.15) 32.65,38.9 32.65,49.95 32,50.6 32,52.35 32.2,52.55 32.2,58.4 31.85,58.75 v1(31.85,60.1) 31.85,60.65 33.65,62.45 v1(35.1,62.45)
  BOTTOM w0.1: v1(84.95,44.2) v1(79.9,44.2) 79.05,45.05 C103.2 77.6,45.1 v1(76.7,45.1) R343.2 ; 62.17,67.22 60.95,66 46.05,66 45.5,65.45 36.9,65.45 35.1,63.65 v1(35.1,62.45) ; v1(84.85,60.4) 84.85,61 84.65,61.2 80,61.2 78.45,62.75 75.8,62.75 74.4,64.15 74.4,68.5 72.9,70 66.8,70 65.4,68.6 63.55,68.6 63.38,68.42 ; UNK5R68.2 78.5,12.5 79.35,13.35 79.35,15.35 79.15,15.55 79.15,19.6 v1(80.25,20.7) ; R327.1 v1(31.85,60.1)
  BOTTOM w0.2: R229.1 v1(85.15,25.05) ; v1(31.9,38.15) R325.1 ; R227.1 v1(84.95,47)
  BOTTOM w0.3: 62.17,67.22 T309.1 63.38,68.42
I2SIN_DATA_C: length 39.9
  TOP w0.1: v1(81.25,21.62) 81.25,32 80.7,32.55 80.7,46.55 80.45,46.8 80.45,49.95 v1(80.8,50.3)
  BOTTOM w0.1: v1(81.25,21.62) 80.12,21.62 78.6,20.1 78.6,15.15 UNK5R69.2 ; v1(80.8,50.3) R104.2 R103.2
I2SIN_LRCK_C: length 172.9
  TOP w0.1: v1(33.45,27.25) 33.45,49 v1(33.65,49.2) 33.45,49.4 33.45,51.95 33.25,52.15 33.25,58.4 34.55,59.7 34.55,60.7 v1(36.35,62.5) ; R108.2 C104.2 72,46.9 72.35,47.25 75.6,47.25 75.95,47.6 R344.2 76.65,47.7 77.15,47.2 77.8,47.2 78.1,47.5 v1(78.25,47.5) ; v1(83.8,38.55) v1(83.8,47.9) 83.9,48 83.9,55.7 83.5,56.1 v1(83.5,57.95) 83.5,60.25 v1(83.65,60.4) ; v1(81.95,20.45) 82.1,20.6 82.1,32.55 81.5,33.15 81.5,47.25 v1(81.25,47.5)
  BOTTOM w0.1: 67.2,67.25 67.05,67.1 63.9,67.1 63,66.2 62.45,66.2 61.45,65.2 46.45,65.2 45.9,64.65 37.35,64.65 36.8,64.1 36.8,62.95 v1(36.35,62.5) ; v1(78.25,47.5) v1(81.25,47.5) 83.4,47.5 v1(83.8,47.9) ; UNK5R67.2 80,12.45 80,13.4 79.85,13.55 79.85,15.7 79.7,15.85 79.7,18.65 81.3,20.25 81.75,20.25 v1(81.95,20.45) ; v1(83.65,60.4) 83.45,60.6 79.4,60.6 78.1,61.9 75.4,61.9 73.5,63.8 73.5,68.15 72.55,69.1 69.05,69.1 68.38,68.42
  BOTTOM w0.2: R228.1 83.6,57.85 v1(83.5,57.95) ; v1(33.65,49.2) 33.65,49.25 33.45,49.45 R328.1 ; R326.1 v1(33.45,27.25) ; v1(83.8,38.55) 83.3,38.05 83.3,35.5 R230.1
  BOTTOM w0.3: 67.2,67.25 T307.1 68.38,68.42
I2SIN_MCLK_B: length 39.5
  TOP w0.1: R102.2 v1(76.6,46.2) ; v1(79.9,46.15) 79.1,45.35 79.1,31.7 79.25,31.55 79.25,22.8 v1(78.8,22.35)
  BOTTOM w0.1: UNK5R70.2 77.15,15.6 78,16.45 78,20.6 78.8,21.4 v1(78.8,22.35) ; v1(76.6,46.2) 76.95,46.55 79.5,46.55 v1(79.9,46.15)
I2SO_DATA0: length 125.3
  TOP w0.1: v1(34.55,61.25) 34.35,61.05 34.35,59.8 33.05,58.5 33.05,52.05 33.25,51.85 33.25,30 v1(33.05,29.8) ; v1(82.95,49.4) 82.75,49.6 82.75,55.19 v1(82.9,55.34) 82.75,55.49 82.75,61.6 v1(83.35,62.2)
  BOTTOM w0.1: R109.2 C105.2 76.85,47.7 R231.2 77.4,48.15 82.65,48.15 83.1,48.6 83.1,49.25 v1(82.95,49.4) ; v1(83.35,62.2) 83.35,62.8 82.45,63.7 R225.2 81.9,63.75 81.4,64.25 75.95,64.25 75.55,64.65 75.55,69.05 73.5,71.1 66.3,71.1 64.9,69.7 61.15,69.7 58.25,66.8 45.65,66.8 45.1,66.25 36.5,66.25 34,63.75 34,61.8 v1(34.55,61.25)
  BOTTOM w0.2: v1(33.05,29.8) 32.4,29.8 32.05,30.15 30.35,30.15 30.16,30.34 U301.7 ; v1(82.9,55.34) 84.65,55.34 85,54.99 86.7,54.99 86.89,54.8 U201.7
I2SO_DATA1: length 120.1
  TOP w0.1: v1(33.95,60.45) 33.95,59.7 32.8,58.55 v1(32.8,51.75) ; v1(82.75,62.2) 82.5,61.95 82.5,48.9 v1(82.65,48.75) 82.7,48.7 82.7,34.1 v1(83.4,33.4)
  BOTTOM w0.1: R110.2 C106.2 76.65,48.75 77,49.1 R231.1 77.4,49.1 78.15,48.35 82.25,48.35 v1(82.65,48.75) ; R226.2 82.3,62.2 v1(82.75,62.2) 83.15,61.8 83.55,61.8 83.75,62 83.75,62.7 82,64.45 76.05,64.45 75.75,64.75 75.75,69.2 73.65,71.3 66.22,71.3 64.82,69.9 61.07,69.9 58.17,67 45.55,67 45,66.45 36.4,66.45 33.8,63.85 33.8,60.6 v1(33.95,60.45)
  BOTTOM w0.2: v1(32.8,51.75) 32.4,51.75 32.05,52.1 30.35,52.1 30.16,52.29 U302.7 ; v1(83.4,33.4) 84.65,33.4 85,33.05 86.7,33.05 86.89,32.86 U202.7
I2SO_MCLK_A: length 1.1
  TOP w0.1: T101.1 R101.2
IR_IN: length 4.6
  TOP w0.1: UNK2T6.1 66.66,52.23
  TOP w0.102: 66.66,52.23 66.66,51.17 66.57,51.08 66.57,50.44 U1.B14
IR_OUT: length 10.5
  TOP w0.102: U1.B13 65.6,50.34 65.94,50.68 65.94,53.11 70.21,57.39 UNK2T5.1
LCD_BL_EN: length 26.4
  TOP w0.1: U1.B1 57.61,50.12 57.22,50.52 57.22,51.09 55.78,52.53 55.78,53.34 55,54.12 55,57.3 54.69,57.61 54.69,63.41 v1(54.4,63.7)
  BOTTOM w0.1: v1(54.4,63.7) 54,64.1 53.5,64.1 53.1,63.7 52.6,63.7 51.8,62.9 44.7,62.9 44.49,63.11
  BOTTOM w0.3: UNK2T21.1 44.49,63.11
LCD_BL_PWM: length 30
  TOP w0.102: v1(52.9,63.1) 52.9,62.6 53.6,61.9 53.6,58.9 53.2,58.5 53.2,57 53.5,56.7 v1(53.5,55.5)
  TOP w0.127: v2(61.95,49.74) 61.94,49.74 61.69,49.48 U1.C7
  BOTTOM w0.1: 44.6,62.2 44.9,62.5 52,62.5 52.6,63.1 v1(52.9,63.1) ; v2(61.95,49.74) 61.95,49.89 61.42,50.42 61.42,52.18 58.45,55.15 56.75,55.15 56.42,55.48 53.52,55.48 v1(53.5,55.5)
  BOTTOM w0.3: 44.6,62.2 UNK2T22.1
LCD_RESET: length 26.1
  TOP w0.1: v1(53.7,63.7) 54.46,62.94 54.46,57.54 54.8,57.2 54.8,54.01 55.57,53.24 55.57,52.43 57.01,50.99 57.01,50.41 57.62,49.8 57.97,49.8 58.3,49.47 U1.C2
  BOTTOM w0.1: v1(53.7,63.7) 54.1,63.3 54.1,62.95 53.85,62.7 52.5,62.7 52.1,62.3 46.7,62.3 46.6,62.2
  BOTTOM w0.3: 46.6,62.2 UNK2T24.1
LINE_OUT_DET: length 25.4
  TOP w0.1: v1(52.9,64.1) 53.3,63.7 53.3,62.8 54.05,62.05 54.05,57.35 54.4,57 54.4,53.8 55.17,53.04 55.17,52.22 56.59,50.8 56.59,50.22 57.66,49.15 58.11,49.15 U1.D2
  BOTTOM w0.1: 46.8,64.4 47,64.6 52.4,64.6 v1(52.9,64.1)
  BOTTOM w0.3: UNK2T23.1 46.8,64.4
LINUX_RX: length 23.7
  TOP w0.1: UNK2D4.1 60.41,65.21 UNK2R1.2
  TOP w0.102: UNK2D4.1 61.94,65.21 63.05,64.1 65.95,64.1 69.19,60.86 69.19,57 65.5,53.32 65.5,51.19 65.27,50.95 65.27,50.45 U1.B12
LINUX_TX: length 32.2
  TOP w0.1: v1(64.1,66.1) 63.2,66.1 62.7,65.6 62.7,64.8 63.15,64.35 64.9,64.35 ; v1(58.05,64.35) 57.75,64.35 57.35,64.75 UNK2D3.1 58.39,65.21 UNK2R16.2
  TOP w0.102: 64.9,64.35 66,64.35 69.4,60.95 69.4,56.91 65.72,53.23 65.72,50.9 U1.A13
  BOTTOM w0.1: v1(64.1,66.1) 63.8,66.1 63.3,65.6 62.8,65.6 61.8,64.6 58.3,64.6 v1(58.05,64.35)
LRCK: length 4.9
  BOTTOM w0.102: UNK5R67.1 79.7,10.95 80.75,9.9 81.55,9.9 82.68,8.77 J813.10
MCLK: length 5.8
  BOTTOM w0.1: J813.14 80.68,8.47 80.45,8.7 78.55,8.7 77.15,10.1 UNK5R70.1
MDDR3_VREF1: length 12.2
  TOP w0.3: v2(56.49,29.24) 56.78,29.53 UNK3U1.H1 ; v2(62.45,25.94) 62.46,25.94 UNK3U1.M8
  BOTTOM w0.254: 56.49,29.19 56.49,29.01 56.59,28.91 ; 56.49,29.19 56.59,29.09 56.59,28.91 ; 56.49,29.19 v2(56.49,29.24) ; UNK3C40.2 61.46,25.9 60.96,26.39 59.92,26.39 58.67,27.64 57.86,27.64 56.59,28.91
  BOTTOM w0.3: v2(56.49,29.24) 56.43,29.24 UNK3C27.2 UNK3R20.2 UNK3R19.1
  BOTTOM w0.4: v2(62.45,25.94) 62.41,25.9 UNK3C40.2
NAND_ALE: length 39.2
  TOP w0.1: 50.9,39.1 50.9,35.65 48.25,33 46.8,33 46.14,32.34 UNK4U5.17 46.14,30.44 45.3,29.6 40.9,29.6 v1(40.7,29.8) ; UNK4U9.U5 v1(42,40.1)
  TOP w0.102: 50.9,39.1 50.9,41.5 51.55,42.15 55.15,42.15 56.52,43.52 57.69,43.52 U1.M1
  BOTTOM w0.1: v1(40.7,29.8) 40.7,34.55 40.3,34.95 40.3,38.4 v1(42,40.1)
NAND_CLE: length 39.5
  TOP w0.1: UNK4U9.W5 42.51,39.54 v1(42.5,39.55) ; v1(41.2,30.15) 41.55,29.8 45.2,29.8 45.64,30.24 UNK4U5.16 45.64,32.19 46.65,33.2 48.15,33.2 50.65,35.7 50.65,41.55 51.5,42.4 55.1,42.4 56.54,43.84 56.85,43.84
  TOP w0.102: U1.L2 58.11,43.94 57.58,43.94 57.48,43.84 56.85,43.84 56.85,43.84
  BOTTOM w0.1: v1(42.5,39.55) 41.75,39.55 41,38.8 41,38.05 40.5,37.55 40.5,35.65 UNK4R14.2 40.9,34.95 40.9,30.45 v1(41.2,30.15)
NAND_CS1: length 36.8
  TOP w0.1: UNK4R11.2 UNK4R11.1 UNK4C3.2 52.39,43.3 51.05,43.3 49.8,42.05 49.8,36.15 47.6,33.95 46.5,33.95 45.95,33.4 42.5,33.4 42.14,33.04 UNK4U5.9 42.14,30.36 v1(42.15,30.35) ; v1(43.66,36) 44.01,36.35 44.01,38.1 UNK4U9.W6
  TOP w0.102: UNK4R11.2 56.03,43.79 56.4,44.16 57.69,44.16 57.69,44.17 U1.L1
  BOTTOM w0.1: v1(43.66,36) 42.76,35.1 UNK4R1.1 v1(42.15,30.35)
NAND_D0: length 28.6
  TOP w0.1: v1(41.5,45) 41.51,44.99 UNK4U9.H3 ; v1(47.65,52.75) 47.64,52.74 UNK4U5.29 47.64,50.3 47.85,50.09 49.01,50.09 49.5,49.6 53.52,49.6 54.07,49.05 UNK4R19.1 UNK4R19.2 55.7,49.05 56.89,47.86 57.95,47.86 58.29,47.52 U1.F2
  BOTTOM w0.1: v1(41.5,45) 42.15,44.35 43.6,44.35 UNK4R16.2 44.4,46.3 44.6,46.5 44.6,50.8 45.01,51.21 47.26,51.21 47.65,51.6 v1(47.65,52.75)
NAND_D1: length 26.9
  TOP w0.1: v1(47.15,52.35) 47.14,52.34 UNK4U5.30 47.14,50.19 47.55,49.79 48.87,49.79 49.6,49.05 UNK4R20.1 UNK4R20.2 53.36,49.05 53.95,48.47 55.78,48.47 56.64,47.6 57.71,47.6 U1.F1 ; v1(42,45.45) 42.01,45.44 UNK4U9.H4
  BOTTOM w0.1: v1(42,45.45) 42,44.85 42.25,44.6 43.2,44.6 43.8,45.2 43.8,46.3 44.3,46.8 44.3,50.9 44.91,51.51 46.31,51.51 v1(47.15,52.35)
NAND_D2: length 26.2
  TOP w0.1: U1.G1 56.86,46.87 55.9,47.83 UNK4R21.2 UNK4R21.1 53.87,47.83 53.34,48.36 49.84,48.36 48.72,49.48 47.34,49.48 46.64,50.19 UNK4U5.31 46.64,52.74 v1(46.65,52.75) ; UNK4U9.H5 42.51,44.99 v1(42.5,45)
  BOTTOM w0.1: v1(46.65,52.75) 46.65,52.24 46.23,51.82 44.81,51.82 43.99,51 43.99,47.2 43.45,46.66 43.45,45.3 43.15,45 v1(42.5,45)
NAND_D3: length 29.6
  TOP w0.1: U1.G2 58.22,46.87 57.88,46.54 56.49,46.54 55.78,47.25 53.95,47.25 53.36,47.83 UNK4R22.2 UNK4R22.1 49.92,47.83 48.57,49.18 47.24,49.18 46.14,50.28 UNK4U5.32 46.14,52.34 v1(46.15,52.35) ; v1(41.5,46.6) 41.15,46.25 40.2,46.25 39.95,46 39.95,44.35 40.2,44.1 UNK4U9.J2
  BOTTOM w0.1: v1(41.5,46.6) 42.45,46.6 43.69,47.84 43.69,51.11 44.7,52.12 45.92,52.12 v1(46.15,52.35)
NAND_D4: length 31.3
  TOP w0.1: UNK4R52.2 41.28,53.32 41.64,52.96 v1(41.64,52.35) UNK4U5.41 41.64,50.21 42.09,49.75 46.26,49.75 47.14,48.87 48.43,48.87 50.05,47.25 53.44,47.25 54.08,46.61 UNK4R23.1 UNK4R23.2 55.62,46.33 57,46.33 57.43,45.9 58.12,45.9 U1.H2 ; v1(40.55,45.8) 41.01,45.34 41.01,44.6 UNK4U9.J3
  BOTTOM w0.1: v1(41.64,52.35) 41.1,51.81 41.1,46.8 40.55,46.25 v1(40.55,45.8)
NAND_D5: length 36.3
  TOP w0.1: v1(39.2,45.8) 39.2,43.45 39.55,43.1 41.01,43.1 UNK4U9.J4 ; U1.J1 57.15,45.57 56.69,46.03 54.02,46.03 53.44,46.61 UNK4R24.2 UNK4R24.1 51.76,46.85 49.95,46.85 48.27,48.53 47.08,48.53 46.17,49.43 41.6,49.43 41.14,49.89 UNK4U5.42 v1(41.14,52.8) 41.14,52.84 40.4,53.58 UNK4R10.2
  BOTTOM w0.1: v1(39.2,45.8) 39.2,45.95 40.2,46.95 40.2,51.86 v1(41.14,52.8)
NAND_D6: length 34.6
  TOP w0.1: UNK4R13.2 39.27,53.15 40.4,53.15 40.64,52.91 UNK4U5.43 v1(40.64,50) 40.64,49.99 41.5,49.13 46.02,49.13 46.95,48.2 48.1,48.2 49.8,46.5 51.3,46.5 51.77,46.03 53.13,46.03 53.77,45.39 UNK4R25.1 UNK4R25.2 55.34,45.39 56.31,45.39 56.44,45.27 58.14,45.27 U1.J2 ; v1(42.5,43.1) 42.51,43.11 UNK4U9.J5
  BOTTOM w0.1: v1(40.64,50) 40.64,46.94 40,46.3 40,44.75 41.65,43.1 v1(42.5,43.1)
NAND_D7: length 39.8
  TOP w0.1: UNK4U9.J6 43.51,44.1 44.01,44.6 44.01,45.34 42.25,47.1 39.7,47.1 v1(39.2,46.6) ; UNK4R2.2 38.3,52.9 39.97,52.9 v1(40.14,52.73) UNK4U5.44 40.14,49.81 41.13,48.82 45.83,48.82 46.75,47.9 47.85,47.9 49.6,46.15 51.35,46.15 52,45.5 UNK4R26.1 UNK4R26.2 53.38,44.91 56.08,44.91 56.09,44.92 U1.K1
  BOTTOM w0.1: v1(40.14,52.73) 40.14,52.19 39.89,51.94 39.89,47.29 v1(39.2,46.6)
NAND_NR/B: length 43
  TOP w0.1: v1(39.15,34.4) 40.64,32.91 UNK4U5.6 40.64,30.68 40.76,30.57 41.02,30.57 41.14,30.69 UNK4U5.7 41.14,32.56 41.1,32.6 41.1,33.25 42.1,34.25 45.6,34.25 46.15,34.8 47.2,34.8 48.6,36.2 48.6,38.9 49.2,39.5 49.2,42.45 v1(51.1,44.35)
  TOP w0.102: v2(59.41,44.59) 59.09,44.92 U1.K3
  BOTTOM w0.1: UNK4R17.1 UNK4R9.1 UNK4R12.1 38.8,34.75 v1(39.15,34.4) ; 52.09,43.36 v1(51.1,44.35)
  BOTTOM w0.102: 52.09,43.36 55.7,43.36 56.33,43.99 56.64,43.99 57.33,44.68 57.93,44.68 58.13,44.88 59.12,44.88 v2(59.41,44.59)
NAND_NRE: length 25.9
  TOP w0.1: UNK4U5.8 41.64,32.46 41.3,32.8 41.3,33.15 42.2,34.05 45.7,34.05 46.25,34.6 47.3,34.6 48.8,36.1 48.8,38.55 v1(49,38.75) ; UNK4R18.2 UNK4R18.1 52.45,40.85 v1(52.45,38.75)
  TOP w0.102: U1.M2 58.11,43.29 56.59,43.29 54.89,41.6 UNK4R18.2
  BOTTOM w0.1: v1(52.45,38.75) v1(49,38.75)
NAND_NWE: length 18.1
  TOP w0.1: UNK4U5.18 46.64,32.44 47,32.8 48.4,32.8 52.85,37.25 52.85,40.15 UNK4R15.1 UNK4R15.2
  TOP w0.102: U1.N1 56.57,42.97 UNK4R15.2
NAND_PSL: length 2.5
  TOP w0.102: UNK4R3.2 42.64,53.43 UNK4U5.39
NAND_VSP: length 3.5
  TOP w0.1: v1(43.58,53.04) 43.71,53.16 UNK4R8.2
  TOP w0.102: v1(43.58,53.04) 43.14,52.59 UNK4U5.38
  BOTTOM w0.1: UNK4R7.2 44.05,53.5 v1(43.58,53.04)
NPWM_OFF1: length 54.2
  TOP w0.1: v1(86.4,14) 85.3,14 83.6,12.3 82.05,12.3 R219.2 ; v1(87.6,57.7) 87.6,35.95 v1(87.75,35.8) 87.6,35.65 87.6,23.65 87,23.05 87,20.25 v1(86.65,19.9)
  BOTTOM w0.1: v1(86.65,19.9) 86.8,19.75 86.8,14.4 v1(86.4,14)
  BOTTOM w0.2: U201.12 88.68,57.37 88.35,57.7 v1(87.6,57.7) ; v1(87.75,35.8) 88.5,35.8 88.68,35.62 U202.12
NPWM_OFF2: length 39.6
  TOP w0.1: v1(29.2,49.4) 29.4,49.2 29.4,47.5 28.95,47.05 28.95,36.85 29.4,36.4 29.4,27.7 v1(29.2,27.5) 29.07,27.38 29.07,22.73 v1(29.27,22.52)
  BOTTOM w0.1: R320.2 36.3,26 35.1,24.8 32.75,24.8 30.1,22.15 29.65,22.15 v1(29.27,22.52)
  BOTTOM w0.2: U302.12 28.37,49.63 28.6,49.4 v1(29.2,49.4) ; v1(29.2,27.5) 28.7,27.5 28.37,27.83 U301.12
NRESET_AMP: length 119.9
  TOP w0.1: v1(35.65,56.85) 36.05,56.45 36.05,27.45 37.35,26.15 39.8,26.15 40.65,25.3 v1(40.65,24.8) ; v1(70.84,16.3) 71.24,16.7 71.9,16.7 72.1,16.9 79.73,16.9 82.03,14.6 R216.1 ; U1.B6 60.71,50.45 60.71,50.99 60.91,51.18 60.91,52.91 60.04,53.77 60.04,59.11 v1(59.7,59.45) ; v1(59.9,17.3) 59.9,17.48 54.05,23.33 54.05,23.75 53.2,24.6 52.6,24.6 v1(52.2,25)
  BOTTOM w0.1: R316.1 v1(40.65,24.8) 40.7,24.8 41.7,25.8 51.4,25.8 v1(52.2,25) ; v1(59.9,17.3) 60.3,16.9 60.85,16.9 61.25,16.5 70.24,16.5 70.44,16.3 v1(70.84,16.3) ; v1(59.7,59.45) 59.5,59.25 50.9,59.25 50.6,59.55 48,59.55 47.6,59.15 47.6,58.25 46.4,57.05 35.85,57.05 v1(35.65,56.85)
NRST_AMP1: length 52.6
  TOP w0.1: R216.2 R215.2 84.05,14 84.8,14 85.4,14.6 R240.2 v1(86.4,14.6) ; v1(86,19.9) 86.8,20.7 86.8,23.45 v1(86.95,23.6) 87.35,24 87.35,45.3 v1(87.2,45.45)
  BOTTOM w0.1: v1(86.4,14.6) 86.55,14.75 86.55,19.35 v1(86,19.9)
  BOTTOM w0.2: v1(86.95,23.6) 86.95,23.55 87,23.5 88.2,23.5 88.35,23.65 88.35,24.55 88.85,25.05 C226.2 90.18,25.61 U202.36 ; v1(87.2,45.45) 88.1,45.45 88.4,45.75 88.4,46.55 88.85,47 C204.2 90.18,47.56 U201.36
